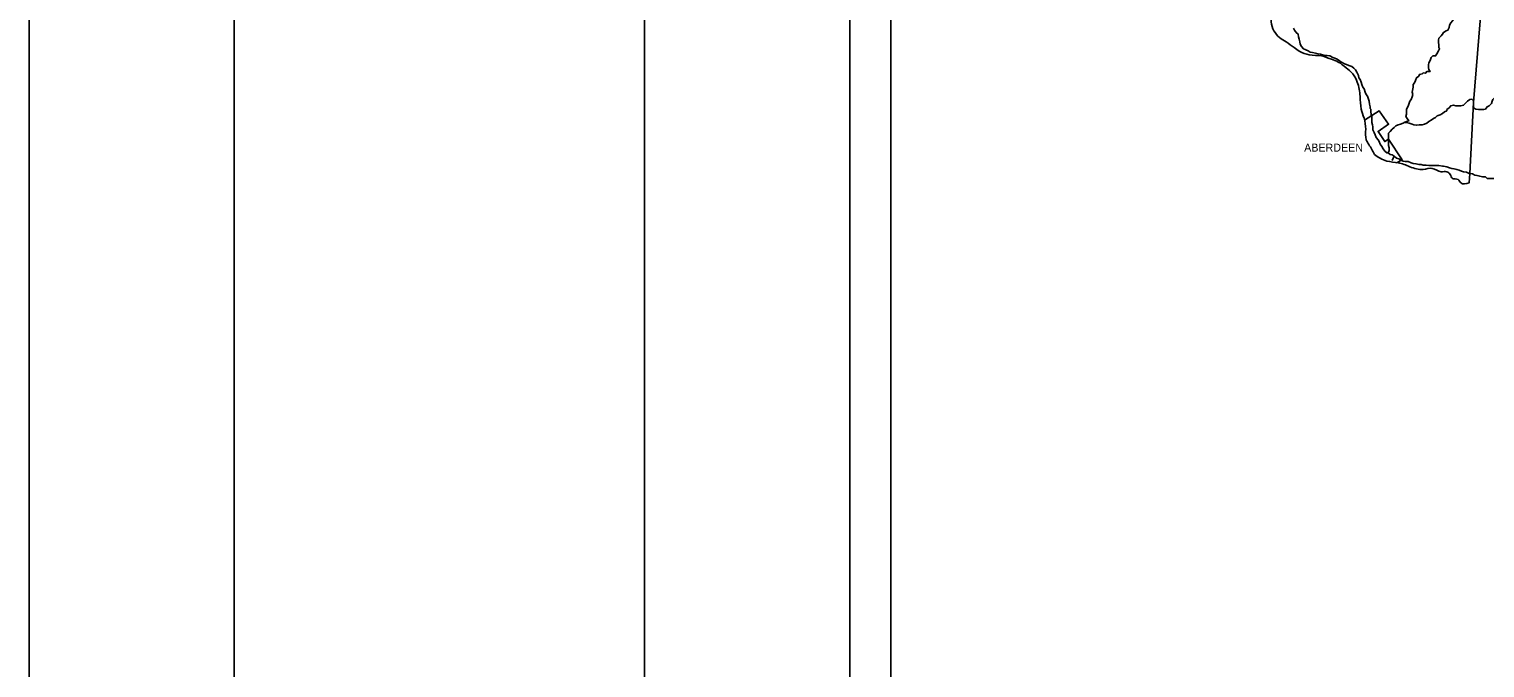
# Model space of a CAD drawing. Extents: x 0 to 40.2, y 0 to 22.
# Drawn here: x 0 to 3.548, y 14.819 to 16.376 of the extents above; entities that cross this region are included whole.
import ezdxf

# ---------------------------------------------------------------- set-up
doc = ezdxf.new("R2010")
doc.units = 0
for name, color, linetype in [('Default', 7, 'Continuous'), ('SH_Border', 7, 'Continuous'), ('SH_Cut_Line', 7, 'Continuous'), ('SH_Data', 7, 'Continuous')]:
    doc.layers.add(name, color=color, linetype=linetype)

msp = doc.modelspace()

# ---------------------------------------------------------------- linework, layer by layer
at = {"layer": 'Default'}
for points in [[(3.6488, 17.7215), (3.6215, 17.4107), (3.5684, 16.7848), (3.5206, 16.1972), (3.5111, 16.0241), (3.5097, 16.0009)], [(3.4443, 16.3635), (3.447, 16.3676), (3.4538, 16.3717), (3.4579, 16.3731), (3.4606, 16.3799), (3.462, 16.3854), (3.4647, 16.3908), (3.4688, 16.3963), (3.4716, 16.4004), (3.4756, 16.4058), (3.4797, 16.4113), (3.4825, 16.4167), (3.4825, 16.4222), (3.4838, 16.429), (3.4852, 16.4358), (3.4879, 16.4413), (3.4906, 16.4467), (3.4934, 16.4522), (3.4961, 16.4576), (3.4988, 16.4631), (3.4961, 16.4672), (3.4934, 16.4699)], [(3.0816, 16.3785), (3.0843, 16.3731), (3.0884, 16.3676), (3.0925, 16.3635), (3.0939, 16.3567), (3.0953, 16.3513), (3.0966, 16.3445), (3.098, 16.339), (3.1007, 16.3336), (3.1062, 16.3281), (3.1116, 16.3254), (3.1171, 16.3226), (3.1225, 16.3199), (3.128, 16.3186), (3.1348, 16.3172), (3.1416, 16.3158), (3.1471, 16.3145), (3.158, 16.3117)], [(3.3979, 16.2695), (3.4034, 16.2681), (3.4061, 16.2722), (3.4143, 16.2722), (3.4116, 16.2777), (3.4102, 16.2817), (3.4102, 16.2886), (3.4116, 16.294), (3.4143, 16.2995), (3.417, 16.3063), (3.4211, 16.3104), (3.4279, 16.3104), (3.4307, 16.3158), (3.4347, 16.3226), (3.4375, 16.3281), (3.4361, 16.3308), (3.4361, 16.3376), (3.4347, 16.3431), (3.4347, 16.3486), (3.4361, 16.354), (3.4416, 16.3595), (3.4443, 16.3635), (3.4443, 16.3635)], [(3.158, 16.3117), (3.1634, 16.3117), (3.1702, 16.3104), (3.1771, 16.3063), (3.1825, 16.3049), (3.188, 16.3022), (3.1934, 16.2981), (3.1989, 16.2954), (3.2057, 16.2913), (3.2111, 16.2899), (3.2166, 16.2872), (3.2234, 16.2845), (3.2289, 16.2804), (3.233, 16.2763), (3.2357, 16.2708), (3.2398, 16.2627), (3.2411, 16.2572), (3.2439, 16.2531), (3.2466, 16.2463), (3.248, 16.2408), (3.2507, 16.234), (3.2534, 16.2299), (3.2561, 16.2218), (3.2589, 16.2163), (3.2616, 16.2122), (3.2643, 16.2054), (3.2657, 16.1999), (3.267, 16.1931), (3.2684, 16.1863), (3.2684, 16.1822), (3.2698, 16.1809)], [(3.3516, 16.1481), (3.357, 16.1509), (3.3625, 16.1522), (3.3584, 16.1577), (3.3557, 16.1631), (3.357, 16.1686), (3.357, 16.1754), (3.357, 16.1809), (3.3611, 16.1877), (3.3625, 16.1931), (3.3652, 16.1999), (3.3679, 16.204), (3.3707, 16.2108), (3.372, 16.2163), (3.3707, 16.2218), (3.372, 16.2299), (3.3734, 16.234), (3.3734, 16.2408), (3.3761, 16.2449), (3.3788, 16.2504), (3.3816, 16.2572), (3.387, 16.2613), (3.3884, 16.2654), (3.3952, 16.2667), (3.3979, 16.2695)], [(3.5206, 16.1972), (3.5206, 16.189), (3.5206, 16.1836), (3.5261, 16.1809), (3.5329, 16.1795), (3.5397, 16.1795), (3.5452, 16.1795), (3.5493, 16.1809), (3.5534, 16.1863), (3.5588, 16.189), (3.5643, 16.1945), (3.5656, 16.1999), (3.567, 16.204), (3.5711, 16.2081), (3.5765, 16.2122), (3.582, 16.2163), (3.5861, 16.2204), (3.5929, 16.2218), (3.5984, 16.2258), (3.6038, 16.2286), (3.6093, 16.2258), (3.6161, 16.2245), (3.6188, 16.2258), (3.6188, 16.2258)], [(3.2698, 16.1809), (3.2698, 16.1754), (3.2711, 16.1672), (3.2725, 16.1631), (3.2725, 16.1563), (3.2725, 16.1481), (3.2739, 16.1427), (3.2752, 16.1372), (3.2752, 16.1304), (3.2779, 16.1236), (3.2807, 16.1181), (3.2834, 16.1113), (3.2875, 16.1059), (3.2902, 16.1018), (3.2929, 16.095), (3.297, 16.0895), (3.2998, 16.084), (3.3039, 16.0786), (3.3093, 16.0745), (3.3093, 16.0745), (3.312, 16.0745)], [(3.3516, 16.1481), (3.357, 16.1481), (3.3638, 16.1468), (3.3707, 16.144), (3.3748, 16.1427), (3.3816, 16.1413), (3.3884, 16.1427), (3.3952, 16.1427), (3.4007, 16.144), (3.4061, 16.1468), (3.4116, 16.1509), (3.417, 16.1536), (3.4225, 16.1577), (3.4279, 16.1604), (3.432, 16.1645), (3.4388, 16.1672), (3.4443, 16.1699), (3.4497, 16.174), (3.4552, 16.1768), (3.4552, 16.1795)], [(3.4552, 16.1795), (3.4606, 16.1836), (3.4647, 16.189), (3.4716, 16.1904), (3.477, 16.189), (3.4838, 16.189), (3.4893, 16.189), (3.4961, 16.1904), (3.5016, 16.1958), (3.5056, 16.1999), (3.5111, 16.204), (3.5165, 16.2054), (3.5206, 16.2013), (3.5206, 16.1972), (3.5206, 16.1972)], [(3.3325, 16.05), (3.3461, 16.0568), (3.3134, 16.1072), (3.3039, 16.1018), (3.2875, 16.1263), (3.3134, 16.144), (3.2902, 16.1768), (3.2548, 16.1536)], [(3.312, 16.0745), (3.3148, 16.08), (3.3148, 16.0868), (3.3134, 16.0922), (3.3134, 16.0977), (3.3134, 16.1031), (3.3134, 16.11), (3.3134, 16.1154), (3.3134, 16.1222), (3.3175, 16.1263), (3.3216, 16.1318), (3.327, 16.1359), (3.3311, 16.1399), (3.3366, 16.1427), (3.342, 16.144), (3.3488, 16.1468), (3.3516, 16.1481)], [(3.327, 16.0663), (3.3216, 16.0691), (3.3175, 16.0704), (3.312, 16.0745)], [(3.312, 16.0745), (3.3175, 16.0704), (3.3216, 16.0691), (3.327, 16.0663)], [(3.3216, 16.0554), (3.3243, 16.0609), (3.327, 16.0663)], [(3.327, 16.0663), (3.3325, 16.0609), (3.3379, 16.0595), (3.342, 16.0568), (3.3488, 16.0541), (3.3543, 16.0527), (3.3611, 16.0527), (3.3679, 16.05), (3.3734, 16.0486), (3.3802, 16.0472), (3.387, 16.0459), (3.3925, 16.0459), (3.3979, 16.0445), (3.4047, 16.0445), (3.4116, 16.0431), (3.4184, 16.0431), (3.4238, 16.0431), (3.4307, 16.0431), (3.4361, 16.0431), (3.4443, 16.0418), (3.447, 16.0418), (3.4552, 16.0404), (3.462, 16.0377), (3.4675, 16.0363), (3.4729, 16.035), (3.4797, 16.0336), (3.4852, 16.0322), (3.4906, 16.0295), (3.4961, 16.0281), (3.5029, 16.0268), (3.5097, 16.0241), (3.5111, 16.0241), (3.5111, 16.0241)], [(3.5111, 16.0241), (3.5179, 16.0227), (3.5234, 16.02), (3.5288, 16.0186), (3.5356, 16.0172), (3.5425, 16.0159), (3.5493, 16.0159), (3.5534, 16.0118), (3.5602, 16.0118), (3.567, 16.0118), (3.5724, 16.0118), (3.5779, 16.0091), (3.5861, 16.0091), (3.5915, 16.0063), (3.597, 16.0036), (3.6024, 16.0036), (3.6093, 16.0009), (3.6161, 15.9995), (3.6202, 15.9982), (3.627, 15.9968), (3.6338, 15.9954), (3.6352, 15.9954), (3.6352, 15.9954)]]:
    msp.add_lwpolyline(points, dxfattribs=at)
msp.add_spline([(3.5097, 16.0009), (3.4893, 16.0009), (3.4825, 16.0091), (3.4688, 16.0118), (3.4634, 16.0213), (3.4552, 16.0281), (3.4416, 16.0281), (3.4197, 16.0363), (3.3979, 16.0336), (3.3652, 16.0404), (3.3366, 16.05), (3.3093, 16.0541), (3.2929, 16.0609), (3.2793, 16.0704), (3.2725, 16.0827), (3.2589, 16.1059), (3.2575, 16.1318), (3.2534, 16.159), (3.2466, 16.1809), (3.2439, 16.2122), (3.237, 16.2463), (3.2261, 16.2667), (3.2098, 16.2817), (3.1907, 16.2954), (3.1743, 16.3022), (3.1498, 16.3104), (3.1198, 16.3131), (3.0966, 16.3213), (3.083, 16.3308), (3.0639, 16.3445), (3.0475, 16.3554), (3.0339, 16.3717), (3.0271, 16.3935), (3.0271, 16.414), (3.0203, 16.4344), (3.0134, 16.4685), (3.0053, 16.4917), (2.9998, 16.5094), (2.9807, 16.5272), (2.9589, 16.5408), (2.9289, 16.5585), (2.9044, 16.5681), (2.8798, 16.5803), (2.8607, 16.5871), (2.8376, 16.5899), (2.8048, 16.594), (2.7762, 16.6008), (2.7489, 16.6035), (2.7271, 16.609), (2.7108, 16.6226), (2.693, 16.6431), (2.6767, 16.6594), (2.644, 16.6744), (2.6099, 16.6799), (2.5731, 16.6853), (2.5308, 16.6785), (2.509, 16.6662), (2.4817, 16.658), (2.4408, 16.6499), (2.4163, 16.6431), (2.389, 16.6294), (2.3563, 16.6226), (2.3276, 16.6171), (2.3072, 16.6103), (2.2867, 16.6144)], degree=3, dxfattribs=at)
at = {"layer": 'SH_Border'}
for points in [[(0.5, 21.5), (1.5, 21.5), (1.5, 0.5), (0.5, 0.5)], [(1.5, 21.5), (33.5, 21.5), (33.5, 0.5), (1.5, 0.5)]]:
    msp.add_lwpolyline(points, close=True, dxfattribs=at)
at = {"layer": 'SH_Cut_Line'}
msp.add_lwpolyline([(0, 0), (34, 0), (34, 22), (0, 22)], close=True, dxfattribs=at)
at = {"layer": 'SH_Data'}
for p, q in [((2, 21), (2, 14)), ((2.1, 20.9), (2.1, 14.1))]:
    msp.add_line(p, q, dxfattribs=at)

# ---------------------------------------------------------------- texts
at = {"layer": 'Default'}
msp.add_text('ABERDEEN', height=0.0195, dxfattribs=at).set_placement((3.1075, 16.0772))

doc.saveas('drawing.dxf')
